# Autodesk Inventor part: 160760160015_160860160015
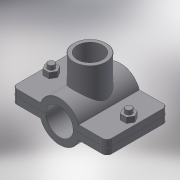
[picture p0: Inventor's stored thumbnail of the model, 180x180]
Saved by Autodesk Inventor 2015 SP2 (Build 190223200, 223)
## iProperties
Created: 2017-05
Part Number: 160760160015_160860160015
Material: Generic
Description: PLASSON SADDLE 160-1.1/2"
Document SubType Name: Modeling
Designer: KIM
Density: 1 g/cm^3
Appearance: Default
Author: KIM
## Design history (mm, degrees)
derived "16076.ipt"
feature "Solid1::16076.ipt"
feature "Solid2::16076.ipt"
tag "TaggingFeature1"
body "Solid1"
other parameters: "d0" = 176, "d1" = 223, "d4" = 145, "d5" = 0, "d6" = 11.15, "d7" = 223, "d8" = 0.1, "d10" = 0, "d11" = 1.6, "d14" = 58.2985, "d20" = 1.6, "d23" = 1.6, "d36" = 15, "d37" = 12, "d38" = 88, "d39" = 0, "d40" = 3, "d41" = 5, "d42" = 0, "d44" = 3, "d45" = 0, "d46" = 1.6, "d51" = 118, "d52" = 44.845, "d53" = 25, "d54" = 0, "d57" = 0, "d58" = 172.8, "d60" = 0, "d62" = 15, "d63" = 12, "d66" = 121, "G_" = 44.845, "A_" = 118, "L_" = 223, "L_1" = 145, "l_2" = 25
